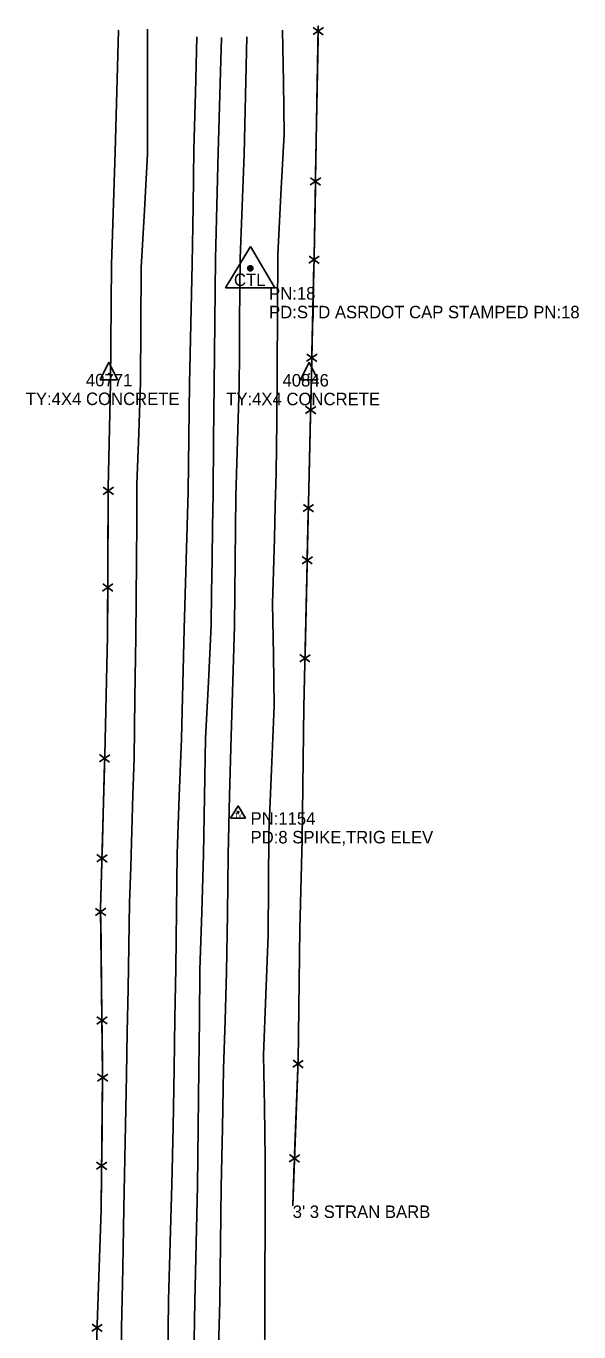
# Model space of a CAD drawing. Extents: x 1445297 to 1476720, y 2042269 to 2057889.
# Drawn here: x 1476181 to 1476403, y 2055966 to 2056489 of the extents above; entities that cross this region are included whole.
import ezdxf

# ---------------------------------------------------------------- set-up
doc = ezdxf.new("R2010")
doc.units = 0
for name, color, linetype in [('S_DITCHLINE', 7, 'Continuous'), ('S_EDGE_PAVEMENT', 7, 'Continuous'), ('S_EXIST_ROW', 7, 'Continuous'), ('S_EXIST_ROW_ANNOT', 7, 'Continuous'), ('S_FENCE', 7, 'Continuous'), ('S_FENCE_ANNOT', 7, 'Continuous'), ('S_MSC_PT_SYM', 7, 'Continuous'), ('S_PAVEMENT_CROWN', 7, 'Continuous'), ('S_PRIMARY_CTL', 7, 'Continuous'), ('S_PRIMARY_CTL_ANNOT', 7, 'Continuous'), ('S_SECONDARY_CTL', 7, 'Continuous'), ('S_SECONDARY_CTL_ANNOT', 7, 'Continuous')]:
    doc.layers.add(name, color=color, linetype=linetype)

msp = doc.modelspace()

# ---------------------------------------------------------------- linework, layer by layer
at = {"layer": 'S_DITCHLINE'}
for points in [[(1476219.19, 2055954.05), (1476219.2, 2055967.83), (1476219.69, 2055991.86), (1476220.19, 2056015.89), (1476220.44, 2056029.22), (1476220.69, 2056042.56), (1476220.95, 2056055.89), (1476221.2, 2056069.23), (1476221.51, 2056086.48), (1476221.82, 2056103.73), (1476222.13, 2056120.98), (1476222.43, 2056138.24), (1476222.89, 2056152.67), (1476223.34, 2056167.11), (1476223.8, 2056181.54), (1476224.25, 2056195.98), (1476224.59, 2056220.37), (1476224.93, 2056244.76), (1476225.05, 2056260.05), (1476225.17, 2056275.34), (1476225.3, 2056290.63), (1476225.42, 2056305.92), (1476226.13, 2056326.33), (1476226.84, 2056346.74), (1476226.99, 2056369.75), (1476227.14, 2056392.76), (1476228.38, 2056415.49), (1476229.62, 2056438.22), (1476229.61, 2056463.16), (1476229.6, 2056488.1)], [(1476276.58, 2055955.76), (1476276.64, 2055971.01), (1476276.71, 2055986.26), (1476276.77, 2056011), (1476276.83, 2056035.75), (1476276.5, 2056056.53), (1476276.17, 2056077.32), (1476277.1, 2056101.34), (1476278.03, 2056125.35), (1476278.13, 2056145.68), (1476278.23, 2056166), (1476278.78, 2056178.78), (1476279.33, 2056191.55), (1476279.88, 2056204.33), (1476280.44, 2056217.1), (1476280.11, 2056237.59), (1476279.79, 2056258.08), (1476280.14, 2056271.13), (1476280.48, 2056284.18), (1476280.83, 2056297.24), (1476281.17, 2056310.29), (1476281.41, 2056331.05), (1476281.65, 2056351.8), (1476281.74, 2056374.76), (1476281.83, 2056397.71), (1476283.12, 2056421.89), (1476284.4, 2056446.08), (1476284.1, 2056466.9), (1476283.8, 2056487.72)]]:
    msp.add_lwpolyline(points, dxfattribs=at)
at = {"layer": 'S_EDGE_PAVEMENT'}
for points in [[(1476237.8, 2055955.33), (1476238.05, 2055979.13), (1476238.74, 2056002.3), (1476239.43, 2056025.47), (1476239.89, 2056048.56), (1476240.35, 2056071.66), (1476240.65, 2056091.87), (1476240.95, 2056112.09), (1476241.21, 2056135), (1476241.46, 2056157.9), (1476242.37, 2056180.91), (1476243.27, 2056203.91), (1476243.82, 2056225.97), (1476244.38, 2056248.03), (1476244.77, 2056261.76), (1476245.16, 2056275.49), (1476245.56, 2056289.22), (1476245.95, 2056302.96), (1476246.21, 2056324.55), (1476246.48, 2056346.15), (1476246.99, 2056370.19), (1476247.5, 2056394.23), (1476247.88, 2056417.13), (1476248.26, 2056440.03), (1476248.84, 2056462.59), (1476249.41, 2056485.14)], [(1476257.96, 2055955), (1476258.58, 2055978.68), (1476258.87, 2056001.61), (1476259.17, 2056024.54), (1476259.64, 2056048.12), (1476260.11, 2056071.7), (1476260.7, 2056091.1), (1476261.28, 2056110.51), (1476261.63, 2056133.99), (1476261.97, 2056157.47), (1476262.56, 2056181.22), (1476263.14, 2056204.97), (1476263.84, 2056227.07), (1476264.54, 2056249.17), (1476264.66, 2056262.16), (1476264.77, 2056275.15), (1476264.88, 2056288.14), (1476264.99, 2056301.13), (1476265.67, 2056323.22), (1476266.35, 2056345.32), (1476266.46, 2056358.09), (1476266.56, 2056370.87), (1476266.67, 2056383.65), (1476266.77, 2056396.42), (1476267.56, 2056417.28), (1476268.34, 2056438.13), (1476268.9, 2056461.6), (1476269.45, 2056485.08)]]:
    msp.add_lwpolyline(points, dxfattribs=at)
at = {"layer": 'S_EXIST_ROW'}
for p, q in [((1476214.14, 2056354.83), (1476210.62, 2056347.74)), ((1476214.14, 2056354.83), (1476217.63, 2056347.74)), ((1476294.48, 2056354.76), (1476290.95, 2056347.67)), ((1476294.48, 2056354.76), (1476297.96, 2056347.67)), ((1476214.13, 2056350.1), (1476214.13, 2056350.1)), ((1476294.46, 2056350.03), (1476294.46, 2056350.03)), ((1476210.62, 2056347.74), (1476217.63, 2056347.74)), ((1476290.95, 2056347.67), (1476297.96, 2056347.67))]:
    msp.add_line(p, q, dxfattribs=at)
for centre, radius in [((1476214.13, 2056350.1), 0.12), ((1476214.13, 2056350.1), 0.06), ((1476294.46, 2056350.03), 0.12), ((1476294.46, 2056350.03), 0.06)]:
    msp.add_circle(centre, radius, dxfattribs=at)
at = {"layer": 'S_FENCE'}
for p, q in [((1476216.7, 2056439.06), (1476217.95, 2056487.61)), ((1476295.97, 2056485.97), (1476300.11, 2056488.76)), ((1476300.06, 2056485.89), (1476296.02, 2056488.83)), ((1476296.43, 2056397.09), (1476298.07, 2056489.32)), ((1476215.26, 2056393.88), (1476216.7, 2056439.06)), ((1476294.89, 2056425.78), (1476299.04, 2056428.58)), ((1476298.99, 2056425.71), (1476294.94, 2056428.65)), ((1476292.3, 2056216.55), (1476296.43, 2056397.09)), ((1476294.32, 2056394.42), (1476298.48, 2056397.2)), ((1476298.41, 2056394.33), (1476294.38, 2056397.29)), ((1476214.74, 2056346.36), (1476215.26, 2056393.88)), ((1476293.42, 2056355.16), (1476297.58, 2056357.93)), ((1476297.51, 2056355.06), (1476293.48, 2056358.02)), ((1476213.93, 2056304.51), (1476214.74, 2056346.36)), ((1476292.94, 2056334.24), (1476297.1, 2056337.02)), ((1476297.04, 2056334.15), (1476293.01, 2056337.11)), ((1476211.86, 2056301.83), (1476215.97, 2056304.67)), ((1476215.96, 2056301.81), (1476211.88, 2056304.7)), ((1476213.62, 2056245.19), (1476213.93, 2056304.51)), ((1476292.04, 2056294.98), (1476296.2, 2056297.75)), ((1476296.14, 2056294.88), (1476292.11, 2056297.84)), ((1476291.56, 2056274.06), (1476295.72, 2056276.84)), ((1476295.66, 2056273.97), (1476291.63, 2056276.93)), ((1476211.66, 2056263.12), (1476215.77, 2056265.97)), ((1476215.76, 2056263.1), (1476211.68, 2056265.99)), ((1476212.47, 2056197.4), (1476213.62, 2056245.19)), ((1476290.67, 2056234.79), (1476294.83, 2056237.57)), ((1476294.76, 2056234.7), (1476290.73, 2056237.66)), ((1476291.57, 2056163.73), (1476292.3, 2056216.55)), ((1476210.35, 2056194.72), (1476214.52, 2056197.48)), ((1476214.44, 2056194.61), (1476210.42, 2056197.59)), ((1476210.86, 2056136.01), (1476212.47, 2056197.4)), ((1476290.63, 2056127.63), (1476291.57, 2056163.73)), ((1476209.3, 2056154.66), (1476213.47, 2056157.42)), ((1476213.4, 2056154.56), (1476209.38, 2056157.53)), ((1476212.94, 2056133.19), (1476208.81, 2056136.01)), ((1476208.85, 2056133.14), (1476212.91, 2056136.06)), ((1476211.66, 2056069.39), (1476210.86, 2056136.01)), ((1476290.04, 2056074.93), (1476290.63, 2056127.63)), ((1476213.47, 2056089.72), (1476209.34, 2056092.54)), ((1476209.37, 2056089.67), (1476213.43, 2056092.59)), ((1476287.83, 2056017.02), (1476290.04, 2056074.93)), ((1476287.89, 2056072.35), (1476292.09, 2056075.06)), ((1476291.98, 2056072.19), (1476288, 2056075.21)), ((1476209.59, 2056066.83), (1476213.71, 2056069.65)), ((1476213.68, 2056066.79), (1476209.62, 2056069.7)), ((1476211.07, 2056015.25), (1476211.66, 2056069.39)), ((1476286.45, 2056034.56), (1476290.65, 2056037.27)), ((1476290.54, 2056034.41), (1476286.56, 2056037.43)), ((1476209.2, 2056031.5), (1476213.32, 2056034.33)), ((1476213.29, 2056031.46), (1476209.23, 2056034.37)), ((1476209.45, 2055969.27), (1476211.07, 2056015.25)), ((1476207.33, 2055966.64), (1476211.5, 2055969.39)), ((1476211.42, 2055966.53), (1476207.4, 2055969.5)), ((1476207.86, 2055910.06), (1476209.45, 2055969.27))]:
    msp.add_line(p, q, dxfattribs=at)
for points in [[(1476216.7, 2056439.06), (1476217.95, 2056487.61)], [(1476297.01, 2056429.92), (1476297.99, 2056484.63)], [(1476215.26, 2056393.88), (1476216.7, 2056439.06)], [(1476296.43, 2056397.09), (1476296.91, 2056424.45)], [(1476214.74, 2056346.36), (1476215.26, 2056393.88)], [(1476295.54, 2056358.33), (1476296.36, 2056394.03)], [(1476295.05, 2056336.91), (1476295.46, 2056354.76)], [(1476213.93, 2056304.51), (1476214.74, 2056346.36)], [(1476294.16, 2056298.15), (1476294.98, 2056333.85)], [(1476213.73, 2056266.3), (1476213.91, 2056301.49)], [(1476293.67, 2056276.73), (1476294.08, 2056294.58)], [(1476292.79, 2056237.97), (1476293.6, 2056273.66)], [(1476213.62, 2056245.19), (1476213.71, 2056262.78)], [(1476212.47, 2056197.4), (1476213.62, 2056245.19)], [(1476292.3, 2056216.55), (1476292.71, 2056234.4)], [(1476291.57, 2056163.73), (1476292.3, 2056216.55)], [(1476211.43, 2056157.86), (1476212.38, 2056194.28)], [(1476290.63, 2056127.63), (1476291.57, 2056163.73)], [(1476210.86, 2056136.01), (1476211.34, 2056154.22)], [(1476211.38, 2056093.1), (1476210.9, 2056132.62)], [(1476290.04, 2056074.93), (1476290.63, 2056127.63)], [(1476211.66, 2056069.39), (1476211.42, 2056089.15)], [(1476288.61, 2056037.63), (1476289.92, 2056071.98)], [(1476211.28, 2056034.52), (1476211.63, 2056066.64)], [(1476211.07, 2056015.25), (1476211.24, 2056031.31)], [(1476287.83, 2056017.02), (1476288.48, 2056034.2)], [(1476209.45, 2055969.27), (1476211.07, 2056015.25)]]:
    msp.add_lwpolyline(points, dxfattribs=at)
at = {"layer": 'S_MSC_PT_SYM'}
for points in [[(1476217.95, 2056487.61), (1476217.95, 2056487.66), (1476217.95, 2056487.61), (1476217.9, 2056487.61), (1476217.95, 2056487.61), (1476217.95, 2056487.56), (1476217.95, 2056487.61), (1476218, 2056487.61)], [(1476298.07, 2056489.32), (1476298.07, 2056489.37), (1476298.07, 2056489.32), (1476298.02, 2056489.32), (1476298.07, 2056489.32), (1476298.07, 2056489.27), (1476298.07, 2056489.32), (1476298.12, 2056489.32)], [(1476216.7, 2056439.06), (1476216.7, 2056439.11), (1476216.7, 2056439.06), (1476216.65, 2056439.06), (1476216.7, 2056439.06), (1476216.7, 2056439.01), (1476216.7, 2056439.06), (1476216.75, 2056439.06)], [(1476296.43, 2056397.09), (1476296.43, 2056397.14), (1476296.43, 2056397.09), (1476296.38, 2056397.09), (1476296.43, 2056397.09), (1476296.43, 2056397.04), (1476296.43, 2056397.09), (1476296.48, 2056397.09)], [(1476215.26, 2056393.88), (1476215.26, 2056393.93), (1476215.26, 2056393.88), (1476215.21, 2056393.88), (1476215.26, 2056393.88), (1476215.26, 2056393.83), (1476215.26, 2056393.88), (1476215.31, 2056393.88)], [(1476214.74, 2056346.36), (1476214.74, 2056346.41), (1476214.74, 2056346.36), (1476214.69, 2056346.36), (1476214.74, 2056346.36), (1476214.74, 2056346.31), (1476214.74, 2056346.36), (1476214.79, 2056346.36)], [(1476213.93, 2056304.51), (1476213.93, 2056304.56), (1476213.93, 2056304.51), (1476213.88, 2056304.51), (1476213.93, 2056304.51), (1476213.93, 2056304.46), (1476213.93, 2056304.51), (1476213.98, 2056304.51)], [(1476213.62, 2056245.19), (1476213.62, 2056245.24), (1476213.62, 2056245.19), (1476213.57, 2056245.19), (1476213.62, 2056245.19), (1476213.62, 2056245.14), (1476213.62, 2056245.19), (1476213.67, 2056245.19)], [(1476292.3, 2056216.55), (1476292.3, 2056216.6), (1476292.3, 2056216.55), (1476292.25, 2056216.55), (1476292.3, 2056216.55), (1476292.3, 2056216.5), (1476292.3, 2056216.55), (1476292.35, 2056216.55)], [(1476212.47, 2056197.4), (1476212.47, 2056197.45), (1476212.47, 2056197.4), (1476212.42, 2056197.4), (1476212.47, 2056197.4), (1476212.47, 2056197.35), (1476212.47, 2056197.4), (1476212.52, 2056197.4)], [(1476291.57, 2056163.73), (1476291.57, 2056163.78), (1476291.57, 2056163.73), (1476291.52, 2056163.73), (1476291.57, 2056163.73), (1476291.57, 2056163.68), (1476291.57, 2056163.73), (1476291.62, 2056163.73)], [(1476210.86, 2056136.01), (1476210.86, 2056136.06), (1476210.86, 2056136.01), (1476210.81, 2056136.01), (1476210.86, 2056136.01), (1476210.86, 2056135.96), (1476210.86, 2056136.01), (1476210.91, 2056136.01)], [(1476290.63, 2056127.63), (1476290.63, 2056127.68), (1476290.63, 2056127.63), (1476290.58, 2056127.63), (1476290.63, 2056127.63), (1476290.63, 2056127.58), (1476290.63, 2056127.63), (1476290.68, 2056127.63)], [(1476290.04, 2056074.93), (1476290.04, 2056074.98), (1476290.04, 2056074.93), (1476289.99, 2056074.93), (1476290.04, 2056074.93), (1476290.04, 2056074.88), (1476290.04, 2056074.93), (1476290.09, 2056074.93)], [(1476211.66, 2056069.39), (1476211.66, 2056069.44), (1476211.66, 2056069.39), (1476211.61, 2056069.39), (1476211.66, 2056069.39), (1476211.66, 2056069.34), (1476211.66, 2056069.39), (1476211.71, 2056069.39)], [(1476211.07, 2056015.25), (1476211.07, 2056015.3), (1476211.07, 2056015.25), (1476211.02, 2056015.25), (1476211.07, 2056015.25), (1476211.07, 2056015.2), (1476211.07, 2056015.25), (1476211.12, 2056015.25)], [(1476287.83, 2056017.02), (1476287.83, 2056017.07), (1476287.83, 2056017.02), (1476287.78, 2056017.02), (1476287.83, 2056017.02), (1476287.83, 2056016.97), (1476287.83, 2056017.02), (1476287.88, 2056017.02)], [(1476209.45, 2055969.27), (1476209.45, 2055969.32), (1476209.45, 2055969.27), (1476209.4, 2055969.27), (1476209.45, 2055969.27), (1476209.45, 2055969.22), (1476209.45, 2055969.27), (1476209.5, 2055969.27)]]:
    msp.add_lwpolyline(points, dxfattribs=at)
at = {"layer": 'S_PAVEMENT_CROWN'}
msp.add_lwpolyline([(1476248.15, 2055955.2), (1476248.64, 2055978.65), (1476249.16, 2056001.76), (1476249.68, 2056024.86), (1476249.95, 2056048.3), (1476250.22, 2056071.75), (1476250.44, 2056091.57), (1476250.66, 2056111.38), (1476251.37, 2056134.46), (1476252.07, 2056157.54), (1476252.49, 2056180.8), (1476252.9, 2056204.05), (1476254.02, 2056226.73), (1476255.14, 2056249.41), (1476255.34, 2056262.54), (1476255.53, 2056275.67), (1476255.73, 2056288.8), (1476255.93, 2056301.92), (1476256.12, 2056323.76), (1476256.3, 2056345.59), (1476256.46, 2056358.23), (1476256.62, 2056370.88), (1476256.77, 2056383.52), (1476256.93, 2056396.16), (1476257.45, 2056417.49), (1476257.98, 2056438.82), (1476258.63, 2056461.85), (1476259.28, 2056484.87)], dxfattribs=at)
at = {"layer": 'S_PRIMARY_CTL'}
for p, q in [((1476270.87, 2056401.05), (1476260.84, 2056384.53)), ((1476270.87, 2056401.05), (1476280.69, 2056384.53)), ((1476260.84, 2056384.53), (1476280.69, 2056384.53))]:
    msp.add_line(p, q, dxfattribs=at)
for radius in [1.04, 0.609, 0.344]:
    msp.add_circle((1476270.87, 2056392.35), radius, dxfattribs=at)
at = {"layer": 'S_SECONDARY_CTL'}
for p, q in [((1476265.93, 2056177.15), (1476262.92, 2056172.19)), ((1476265.93, 2056177.15), (1476268.88, 2056172.19)), ((1476262.92, 2056172.19), (1476268.88, 2056172.19))]:
    msp.add_line(p, q, dxfattribs=at)
for radius in [0.311, 0.183, 0.103]:
    msp.add_circle((1476265.93, 2056174.54), radius, dxfattribs=at)

# ---------------------------------------------------------------- texts
at = {"layer": 'S_EXIST_ROW_ANNOT'}
for s, p in [('40771', (1476204.96, 2056345.1)), ('40846', (1476283.74, 2056345.03)), ('TY:4X4 CONCRETE', (1476180.82, 2056337.6)), ('TY:4X4 CONCRETE', (1476261.16, 2056337.53))]:
    msp.add_text(s, height=5, dxfattribs=at).set_placement(p)
at = {"layer": 'S_FENCE_ANNOT'}
msp.add_text("3' 3 STRAN BARB", height=5, dxfattribs=at).set_placement((1476287.83, 2056012.02))
at = {"layer": 'S_PRIMARY_CTL'}
msp.add_text('CTL', height=5, dxfattribs=at).set_placement((1476264.28, 2056385.27))
at = {"layer": 'S_PRIMARY_CTL_ANNOT'}
for s, p in [('PN:18', (1476278.37, 2056379.85)), ('PD:STD ASRDOT CAP STAMPED PN:18', (1476278.37, 2056372.35))]:
    msp.add_text(s, height=5, dxfattribs=at).set_placement(p)
at = {"layer": 'S_SECONDARY_CTL'}
msp.add_text('TV', height=1.5, dxfattribs=at).set_placement((1476264.73, 2056172.53))
at = {"layer": 'S_SECONDARY_CTL_ANNOT'}
for s, p in [('PN:1154', (1476270.93, 2056169.54)), ('PD:8 SPIKE,TRIG ELEV', (1476270.93, 2056162.04))]:
    msp.add_text(s, height=5, dxfattribs=at).set_placement(p)

doc.saveas('drawing.dxf')
